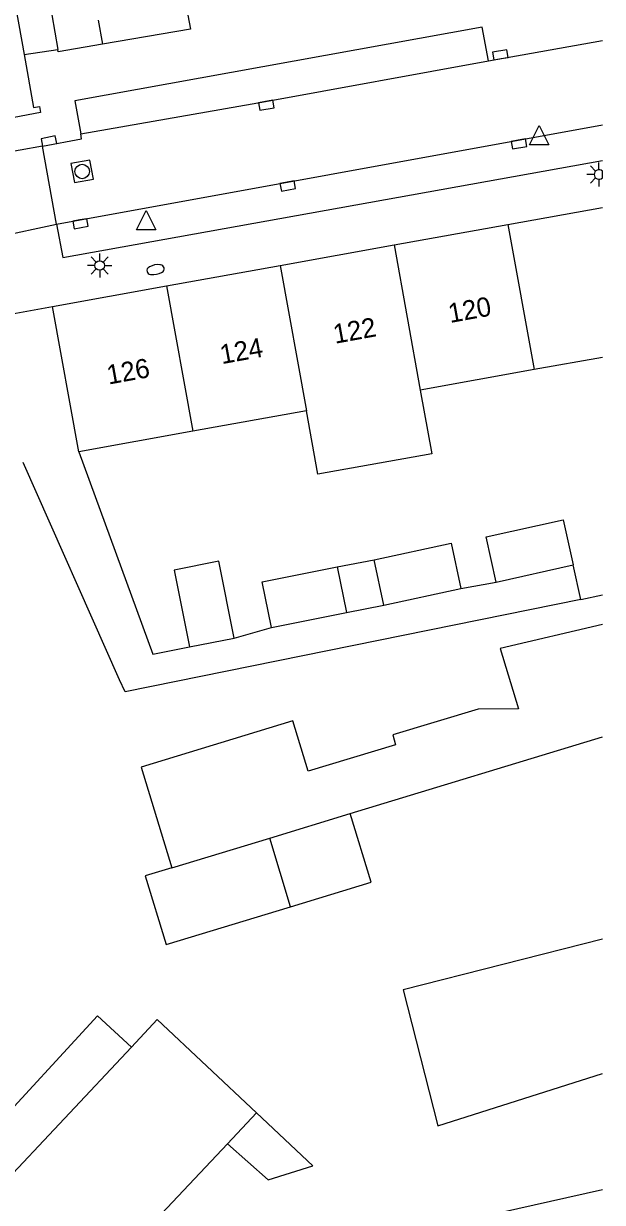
# Model space of a CAD drawing. Extents: x 132573 to 132944, y 398226 to 398676.
# Drawn here: x 132910.1 to 132940.1, y 398438.1 to 398499.2 of the extents above; entities that cross this region are included whole.
import ezdxf

# ---------------------------------------------------------------- set-up
doc = ezdxf.new("R2010")
doc.units = 0
for name, color, linetype in [('gg-afsc-erfafscheiding', 7, 'Continuous'), ('gg-afsc-hekwerk', 7, 'Continuous'), ('gg-anno-huisnummerreeks BGT', 7, 'Continuous'), ('gg-bbg-bijgebouw', 7, 'Continuous'), ('gg-bbg-gedigitaliseerde bebouwing', 7, 'Continuous'), ('gg-bbg-gedigitaliseerde bijgebouw', 7, 'Continuous'), ('gg-bbg-hoofdgebouw', 7, 'Continuous'), ('gg-bbg-luifel en loopbrug', 7, 'Continuous'), ('gg-bbg-tussenscheiding', 7, 'Continuous'), ('gg-knt-verharding', 7, 'Continuous'), ('gg-knt-verharding nz', 7, 'Continuous'), ('gt-symb-brandkraan', 7, 'Continuous'), ('gt-symb-kolk', 7, 'Continuous'), ('gt-symb-lichtmast', 7, 'Continuous'), ('gt-symb-rioolschacht', 7, 'Continuous'), ('gt-symb-waterafsluiter', 7, 'Continuous')]:
    doc.layers.add(name, color=color, linetype=linetype)

msp = doc.modelspace()

# ---------------------------------------------------------------- linework, layer by layer
at = {"layer": 'gg-afsc-erfafscheiding'}
for p, q in [((132938.989, 398469.328), (132938.597, 398471.126)), ((132932.781, 398469.906), (132934.599, 398470.243)), ((132938.989, 398469.328), (132940.113, 398469.573)), ((132921.031, 398467.336), (132922.959, 398467.883))]:
    msp.add_line(p, q, dxfattribs=at)
for points in [[(132912.972, 398476.999), (132916.817, 398466.509), (132918.719, 398466.873)], [(132938.989, 398469.328), (132915.384, 398464.55), (132915.077, 398465.165), (132910.089, 398476.44)]]:
    msp.add_lwpolyline(points, dxfattribs=at)
at = {"layer": 'gg-afsc-hekwerk'}
msp.add_line((132910.135, 398497.605), (132911.885, 398497.862), dxfattribs=at)
at = {"layer": 'gg-bbg-bijgebouw'}
for p, q in [((132914.203, 398498.133), (132911.907, 398497.734)), ((132911.907, 398497.734), (132911.885, 398497.862))]:
    msp.add_line(p, q, dxfattribs=at)
at = {"layer": 'gg-bbg-gedigitaliseerde bebouwing'}
for p, q in [((132912.972, 398476.999), (132911.61, 398484.53)), ((132940.113, 398481.896), (132936.57, 398481.257)), ((132936.57, 398481.257), (132930.671, 398480.192)), ((132924.773, 398479.128), (132918.876, 398478.064)), ((132918.876, 398478.064), (132912.972, 398476.999)), ((132920.68, 398441.107), (132922.185, 398442.709)), ((132917.26, 398437.467), (132920.68, 398441.107))]:
    msp.add_line(p, q, dxfattribs=at)
for points in [[(132930.671, 398480.192), (132931.266, 398476.895), (132925.368, 398475.831), (132924.773, 398479.128)], [(132906.296, 398443.344), (132908.234, 398441.559), (132913.937, 398447.75), (132915.701, 398446.125)], [(132922.185, 398442.709), (132917.037, 398447.546), (132915.701, 398446.125)]]:
    msp.add_lwpolyline(points, dxfattribs=at)
at = {"layer": 'gg-bbg-gedigitaliseerde bijgebouw'}
for p, q in [((132910.803, 398504.077), (132911.885, 398497.862)), ((132913.97, 398499.388), (132914.203, 398498.133)), ((132928.791, 398469.045), (132928.284, 398471.394)), ((132926.371, 398471.028), (132926.846, 398468.664)), ((132934.599, 398470.243), (132938.597, 398471.126)), ((132928.791, 398469.045), (132932.781, 398469.906)), ((132922.959, 398467.883), (132926.846, 398468.664)), ((132918.719, 398466.873), (132921.031, 398467.336)), ((132927.036, 398458.233), (132940.113, 398462.211)), ((132922.867, 398456.966), (132927.036, 398458.233)), ((132923.952, 398453.4), (132922.867, 398456.966)), ((132940.113, 398451.714), (132929.788, 398449.083)), ((132933.873, 398437.331), (132940.113, 398438.728))]:
    msp.add_line(p, q, dxfattribs=at)
for points in [[(132934.599, 398470.243), (132934.082, 398472.585), (132938.08, 398473.468), (132938.597, 398471.126)], [(132928.284, 398471.394), (132932.274, 398472.255), (132932.781, 398469.906)], [(132921.031, 398467.336), (132920.232, 398471.324), (132917.92, 398470.861), (132918.719, 398466.873)], [(132922.959, 398467.883), (132922.484, 398470.247), (132926.371, 398471.028)], [(132940.113, 398468.032), (132934.815, 398466.799), (132935.767, 398463.668), (132933.667, 398463.656), (132929.244, 398462.311), (132929.397, 398461.805), (132924.862, 398460.426)], [(132924.862, 398460.426), (132924.068, 398463.038), (132916.2, 398460.645), (132917.789, 398455.421)], [(132917.789, 398455.421), (132916.42, 398455.005), (132917.504, 398451.439), (132923.952, 398453.4)], [(132929.788, 398449.083), (132931.584, 398442.034), (132940.113, 398444.753)]]:
    msp.add_lwpolyline(points, dxfattribs=at)
at = {"layer": 'gg-bbg-hoofdgebouw'}
for p, q in [((132909.704, 398500), (132910.135, 398497.605)), ((132935.21, 398488.789), (132940.113, 398489.674)), ((132929.312, 398487.724), (132935.21, 398488.789)), ((132923.414, 398486.66), (132929.312, 398487.724)), ((132917.516, 398485.596), (132923.414, 398486.66)), ((132911.61, 398484.53), (132917.516, 398485.596))]:
    msp.add_line(p, q, dxfattribs=at)
for points in [[(132910.135, 398497.605), (132910.63, 398494.85), (132910.93, 398494.91)], [(132910.93, 398494.91), (132910.98, 398494.59), (132904.422, 398493.346)]]:
    msp.add_lwpolyline(points, dxfattribs=at)
at = {"layer": 'gg-bbg-luifel en loopbrug'}
for p, q in [((132926.371, 398471.028), (132928.284, 398471.394)), ((132926.846, 398468.664), (132928.791, 398469.045))]:
    msp.add_line(p, q, dxfattribs=at)
for points in [[(132918.63, 398499.639), (132918.757, 398498.925), (132914.203, 398498.133)], [(132923.952, 398453.4), (132928.12, 398454.668), (132927.036, 398458.233)], [(132920.68, 398441.107), (132922.789, 398439.23), (132925.103, 398439.967), (132922.185, 398442.709)]]:
    msp.add_lwpolyline(points, dxfattribs=at)
at = {"layer": 'gg-bbg-tussenscheiding'}
for p, q in [((132935.21, 398488.789), (132936.57, 398481.257)), ((132929.312, 398487.724), (132930.671, 398480.192)), ((132923.414, 398486.66), (132924.773, 398479.128)), ((132917.516, 398485.596), (132918.876, 398478.064)), ((132917.789, 398455.421), (132922.867, 398456.966)), ((132904.67, 398434.38), (132915.701, 398446.125))]:
    msp.add_line(p, q, dxfattribs=at)
at = {"layer": 'gg-knt-verharding'}
for p, q in [((132934.202, 398497.266), (132940.113, 398498.329)), ((132911.097, 398492.846), (132906.375, 398492.008)), ((132911.811, 398488.804), (132911.097, 398492.846)), ((132907.157, 398487.801), (132911.811, 398488.804)), ((132908.72, 398484.01), (132911.61, 398484.53))]:
    msp.add_line(p, q, dxfattribs=at)
for points in [[(132934.202, 398497.266), (132933.888, 398499.025), (132912.766, 398495.208), (132913.085, 398493.48)], [(132911.097, 398492.846), (132913.119, 398493.227), (132913.085, 398493.48)], [(132911.811, 398488.804), (132912.143, 398487.074), (132940.113, 398492.097)]]:
    msp.add_lwpolyline(points, dxfattribs=at)
at = {"layer": 'gg-knt-verharding nz'}
msp.add_line((132911.811, 398488.804), (132940.113, 398493.958), dxfattribs=at)
msp.add_lwpolyline([(132913.085, 398493.48), (132922.659, 398495.169), (132934.202, 398497.266)], dxfattribs=at)
at = {"layer": 'gt-symb-brandkraan'}
for centre, radius, start, end in [((132916.712, 398486.396), 0.206, 118.80948, 263.67561), ((132918.058, 398483.948), 3, 118.13459, 118.80948), ((132917.086, 398485.767), 0.938, 84.3505, 118.13459), ((132916.883, 398483.714), 3, 83.6756, 84.3505), ((132917.19, 398486.492), 0.206, 298.80946, 83.6756), ((132917.019, 398489.174), 3, 263.67561, 264.35051), ((132916.816, 398487.121), 0.938, 264.35051, 298.13457), ((132915.844, 398488.94), 3, 298.13457, 298.80946)]:
    msp.add_arc(centre, radius, start, end, dxfattribs=at)
at = {"layer": 'gt-symb-kolk'}
for points in [[(132934.862, 398497.389), (132935.231, 398497.455), (132935.161, 398497.849), (132934.422, 398497.717), (132934.493, 398497.323), (132934.862, 398497.389)], [(132922.659, 398495.169), (132922.29, 398495.104), (132922.359, 398494.71), (132923.098, 398494.84), (132923.028, 398495.234), (132922.659, 398495.169)], [(132911.463, 398492.913), (132911.831, 398492.983), (132911.757, 398493.376), (132911.02, 398493.236), (132911.095, 398492.843), (132911.463, 398492.913)], [(132935.752, 398493.164), (132935.383, 398493.098), (132935.454, 398492.704), (132936.192, 398492.837), (132936.121, 398493.23), (132935.752, 398493.164)], [(132923.77, 398490.982), (132923.401, 398490.915), (132923.472, 398490.522), (132924.21, 398490.655), (132924.139, 398491.049), (132923.77, 398490.982)], [(132913.027, 398489.021), (132912.658, 398488.955), (132912.729, 398488.561), (132913.467, 398488.694), (132913.396, 398489.087), (132913.027, 398489.021)]]:
    msp.add_lwpolyline(points, dxfattribs=at)
at = {"layer": 'gt-symb-lichtmast'}
for p, q in [((132939.759, 398491.555), (132939.494, 398491.82)), ((132939.936, 398491.628), (132939.936, 398492.003)), ((132940.113, 398491.202), (132940.113, 398491.554)), ((132939.686, 398491.378), (132939.311, 398491.378)), ((132939.759, 398491.201), (132939.494, 398490.936)), ((132939.936, 398491.128), (132939.936, 398490.753)), ((132914.058, 398486.909), (132914.058, 398487.284)), ((132913.808, 398486.659), (132913.433, 398486.659)), ((132913.881, 398486.836), (132913.616, 398487.101)), ((132914.235, 398486.836), (132914.5, 398487.101)), ((132914.308, 398486.659), (132914.683, 398486.659)), ((132913.881, 398486.482), (132913.616, 398486.217)), ((132914.058, 398486.409), (132914.058, 398486.034)), ((132914.5, 398486.217), (132914.235, 398486.482))]:
    msp.add_line(p, q, dxfattribs=at)
msp.add_circle((132914.058, 398486.659), 0.25, dxfattribs=at)
msp.add_arc((132939.936, 398491.378), 0.25, 44.90796, 315.09204, dxfattribs=at)
at = {"layer": 'gt-symb-rioolschacht'}
msp.add_lwpolyline([(132913.553, 398492.117), (132912.568, 398491.942), (132912.743, 398490.957), (132913.728, 398491.132)], close=True, dxfattribs=at)
msp.add_circle((132913.148, 398491.537), 0.375, dxfattribs=at)
at = {"layer": 'gt-symb-waterafsluiter'}
for p, q in [((132936.329, 398492.918), (132936.829, 398493.918)), ((132936.829, 398493.918), (132937.329, 398492.918)), ((132937.329, 398492.918), (132936.329, 398492.918)), ((132915.972, 398488.513), (132916.472, 398489.513)), ((132916.472, 398489.513), (132916.972, 398488.513)), ((132916.972, 398488.513), (132915.972, 398488.513))]:
    msp.add_line(p, q, dxfattribs=at)

# ---------------------------------------------------------------- texts
at = {"layer": 'gg-anno-huisnummerreeks BGT'}
for s, p in [('120', (132932.219, 398483.675)), ('122', (132926.256, 398482.598)), ('124', (132920.387, 398481.54)), ('126', (132914.519, 398480.481))]:
    msp.add_text(s, height=1, rotation=10.3, dxfattribs=at).set_placement(p)

doc.saveas('drawing.dxf')
